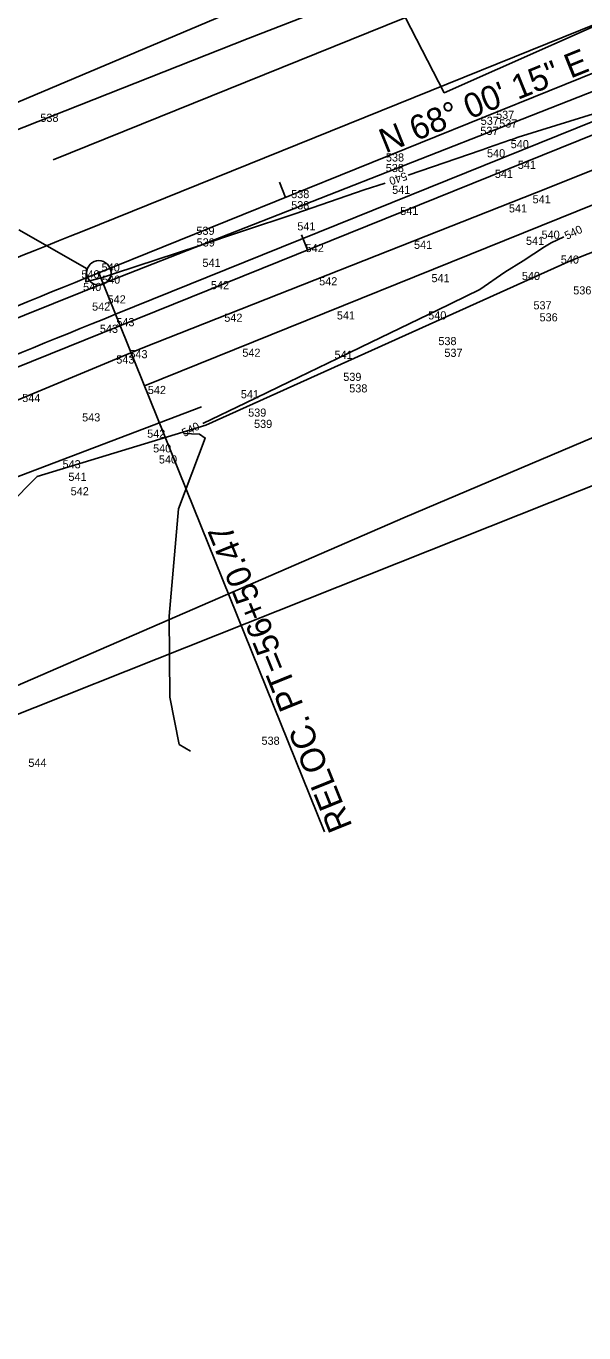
# Model space of a CAD drawing. Extents: x 1787461 to 1970323, y 938412 to 1118748.
# Drawn here: x 1967349.3 to 1967486.5, y 1117453.4 to 1117774.7 of the extents above; entities that cross this region are included whole.
import ezdxf

# ---------------------------------------------------------------- set-up
doc = ezdxf.new("R2010")
doc.units = 0
for name, color, linetype in [('Default', 7, 'Continuous'), ('HHA ADDITIONAL XSs', 7, 'Continuous'), ('Level 1', 7, 'Continuous'), ('RD_EX_DV_Prop', 7, 'Continuous'), ('RD_EX_Fence_Other', 7, 'Continuous'), ('RD_EX_Road', 7, 'Continuous'), ('RD_EX_VEG', 7, 'Continuous'), ('RD_HC_CL', 7, 'Continuous'), ('RD_HC_CL_Rel', 7, 'Continuous'), ('RD_HC_Data_Rel', 7, 'Continuous'), ('RD_HC_Data_Tic', 7, 'Continuous'), ('RD_HC_Data_Tic_Rel', 7, 'Continuous'), ('RD_PD_Final_TrvlWay', 7, 'Continuous')]:
    doc.layers.add(name, color=color, linetype=linetype)

msp = doc.modelspace()

# ---------------------------------------------------------------- linework, layer by layer
at = {"layer": 'Default'}
for points in [[(1967443.31, 1117738.03), (1967461.28, 1117744.21), (1967462.61, 1117744.65), (1967462.8, 1117744.72), (1967468.49, 1117746.69), (1967468.6, 1117746.73), (1967470.34, 1117747.38), (1967492.34, 1117754.16), (1967503.68, 1117757.74), (1967516.18, 1117761.63), (1967538.47, 1117768.72)], [(1967443.31, 1117738.03), (1967461.28, 1117744.21), (1967462.61, 1117744.65), (1967462.8, 1117744.72), (1967468.49, 1117746.69), (1967468.6, 1117746.73), (1967470.34, 1117747.38), (1967492.34, 1117754.16), (1967503.68, 1117757.74), (1967516.18, 1117761.63), (1967538.47, 1117768.72)], [(1967443.31, 1117738.03), (1967461.28, 1117744.21), (1967462.61, 1117744.65), (1967462.8, 1117744.72), (1967468.49, 1117746.69), (1967468.6, 1117746.73), (1967470.34, 1117747.38), (1967492.34, 1117754.16), (1967503.68, 1117757.74), (1967516.18, 1117761.63), (1967538.47, 1117768.72)], [(1967443.31, 1117738.03), (1967461.28, 1117744.21), (1967462.61, 1117744.65), (1967462.8, 1117744.72), (1967468.49, 1117746.69), (1967468.6, 1117746.73), (1967470.34, 1117747.38), (1967492.34, 1117754.16), (1967503.68, 1117757.74), (1967516.18, 1117761.63), (1967538.47, 1117768.72)], [(1967443.31, 1117738.03), (1967461.28, 1117744.21), (1967462.61, 1117744.65), (1967462.8, 1117744.72), (1967468.49, 1117746.69), (1967468.6, 1117746.73), (1967470.34, 1117747.38), (1967492.34, 1117754.16), (1967503.68, 1117757.74), (1967516.18, 1117761.63), (1967538.47, 1117768.72)], [(1967443.31, 1117738.03), (1967461.28, 1117744.21), (1967462.61, 1117744.65), (1967462.8, 1117744.72), (1967468.49, 1117746.69), (1967468.6, 1117746.73), (1967470.34, 1117747.38), (1967492.34, 1117754.16), (1967503.68, 1117757.74), (1967516.18, 1117761.63), (1967538.47, 1117768.72)], [(1967443.31, 1117738.03), (1967461.28, 1117744.21), (1967462.61, 1117744.65), (1967462.8, 1117744.72), (1967468.49, 1117746.69), (1967468.6, 1117746.73), (1967470.34, 1117747.38), (1967492.34, 1117754.16), (1967503.68, 1117757.74), (1967516.18, 1117761.63), (1967538.47, 1117768.72)], [(1967347.55, 1117724.58), (1967362.59, 1117715.97), (1967364.17, 1117715.07), (1967364.17, 1117714.33), (1967363.99, 1117711.78), (1967368.14, 1117712.87), (1967371.08, 1117713.86), (1967391.79, 1117720.64), (1967402.55, 1117724.29), (1967415.42, 1117728.54), (1967432.48, 1117734.38), (1967437.63, 1117736.09)], [(1967347.55, 1117724.58), (1967362.59, 1117715.97), (1967364.17, 1117715.07), (1967364.17, 1117714.33), (1967363.99, 1117711.78), (1967368.14, 1117712.87), (1967371.08, 1117713.86), (1967391.79, 1117720.64), (1967402.55, 1117724.29), (1967415.42, 1117728.54), (1967432.48, 1117734.38), (1967437.63, 1117736.09)], [(1967347.55, 1117724.58), (1967362.59, 1117715.97), (1967364.17, 1117715.07), (1967364.17, 1117714.33), (1967363.99, 1117711.78), (1967368.14, 1117712.87), (1967371.08, 1117713.86), (1967391.79, 1117720.64), (1967402.55, 1117724.29), (1967415.42, 1117728.54), (1967432.48, 1117734.38), (1967437.63, 1117736.09)], [(1967347.55, 1117724.58), (1967362.59, 1117715.97), (1967364.17, 1117715.07), (1967364.17, 1117714.33), (1967363.99, 1117711.78), (1967368.14, 1117712.87), (1967371.08, 1117713.86), (1967391.79, 1117720.64), (1967402.55, 1117724.29), (1967415.42, 1117728.54), (1967432.48, 1117734.38), (1967437.63, 1117736.09)], [(1967347.55, 1117724.58), (1967362.59, 1117715.97), (1967364.17, 1117715.07), (1967364.17, 1117714.33), (1967363.99, 1117711.78), (1967368.14, 1117712.87), (1967371.08, 1117713.86), (1967391.79, 1117720.64), (1967402.55, 1117724.29), (1967415.42, 1117728.54), (1967432.48, 1117734.38), (1967437.63, 1117736.09)], [(1967347.55, 1117724.58), (1967362.59, 1117715.97), (1967364.17, 1117715.07), (1967364.17, 1117714.33), (1967363.99, 1117711.78), (1967368.14, 1117712.87), (1967371.08, 1117713.86), (1967391.79, 1117720.64), (1967402.55, 1117724.29), (1967415.42, 1117728.54), (1967432.48, 1117734.38), (1967437.63, 1117736.09)], [(1967347.55, 1117724.58), (1967362.59, 1117715.97), (1967364.17, 1117715.07), (1967364.17, 1117714.33), (1967363.99, 1117711.78), (1967368.14, 1117712.87), (1967371.08, 1117713.86), (1967391.79, 1117720.64), (1967402.55, 1117724.29), (1967415.42, 1117728.54), (1967432.48, 1117734.38), (1967437.63, 1117736.09)], [(1967481.54, 1117722.84), (1967478.43, 1117721.37), (1967476.85, 1117720.41), (1967471.57, 1117716.93), (1967467.04, 1117714.14), (1967460.9, 1117709.88), (1967450.32, 1117704.75), (1967448.49, 1117703.86), (1967431.69, 1117695.71), (1967425.94, 1117692.94), (1967414.04, 1117687.18), (1967403.38, 1117682.06), (1967392.83, 1117676.99)], [(1967481.54, 1117722.84), (1967478.43, 1117721.37), (1967476.85, 1117720.41), (1967471.57, 1117716.93), (1967467.04, 1117714.14), (1967460.9, 1117709.88), (1967450.32, 1117704.75), (1967448.49, 1117703.86), (1967431.69, 1117695.71), (1967425.94, 1117692.94), (1967414.04, 1117687.18), (1967403.38, 1117682.06), (1967392.83, 1117676.99)], [(1967481.54, 1117722.84), (1967478.43, 1117721.37), (1967476.85, 1117720.41), (1967471.57, 1117716.93), (1967467.04, 1117714.14), (1967460.9, 1117709.88), (1967450.32, 1117704.75), (1967448.49, 1117703.86), (1967431.69, 1117695.71), (1967425.94, 1117692.94), (1967414.04, 1117687.18), (1967403.38, 1117682.06), (1967392.83, 1117676.99)], [(1967481.54, 1117722.84), (1967478.43, 1117721.37), (1967476.85, 1117720.41), (1967471.57, 1117716.93), (1967467.04, 1117714.14), (1967460.9, 1117709.88), (1967450.32, 1117704.75), (1967448.49, 1117703.86), (1967431.69, 1117695.71), (1967425.94, 1117692.94), (1967414.04, 1117687.18), (1967403.38, 1117682.06), (1967392.83, 1117676.99)], [(1967481.54, 1117722.84), (1967478.43, 1117721.37), (1967476.85, 1117720.41), (1967471.57, 1117716.93), (1967467.04, 1117714.14), (1967460.9, 1117709.88), (1967450.32, 1117704.75), (1967448.49, 1117703.86), (1967431.69, 1117695.71), (1967425.94, 1117692.94), (1967414.04, 1117687.18), (1967403.38, 1117682.06), (1967392.83, 1117676.99)], [(1967481.54, 1117722.84), (1967478.43, 1117721.37), (1967476.85, 1117720.41), (1967471.57, 1117716.93), (1967467.04, 1117714.14), (1967460.9, 1117709.88), (1967450.32, 1117704.75), (1967448.49, 1117703.86), (1967431.69, 1117695.71), (1967425.94, 1117692.94), (1967414.04, 1117687.18), (1967403.38, 1117682.06), (1967392.83, 1117676.99)], [(1967481.54, 1117722.84), (1967478.43, 1117721.37), (1967476.85, 1117720.41), (1967471.57, 1117716.93), (1967467.04, 1117714.14), (1967460.9, 1117709.88), (1967450.32, 1117704.75), (1967448.49, 1117703.86), (1967431.69, 1117695.71), (1967425.94, 1117692.94), (1967414.04, 1117687.18), (1967403.38, 1117682.06), (1967392.83, 1117676.99)], [(1967388.04, 1117674.52), (1967391.98, 1117674.37), (1967393.4, 1117673.39), (1967386.8, 1117655.96), (1967384.55, 1117629.59), (1967384.67, 1117609.63), (1967387, 1117598.04), (1967389.76, 1117596.36)], [(1967388.04, 1117674.52), (1967391.98, 1117674.37), (1967393.4, 1117673.39), (1967386.8, 1117655.96), (1967384.55, 1117629.59), (1967384.67, 1117609.63), (1967387, 1117598.04), (1967389.76, 1117596.36)], [(1967388.04, 1117674.52), (1967391.98, 1117674.37), (1967393.4, 1117673.39), (1967386.8, 1117655.96), (1967384.55, 1117629.59), (1967384.67, 1117609.63), (1967387, 1117598.04), (1967389.76, 1117596.36)], [(1967388.04, 1117674.52), (1967391.98, 1117674.37), (1967393.4, 1117673.39), (1967386.8, 1117655.96), (1967384.55, 1117629.59), (1967384.67, 1117609.63), (1967387, 1117598.04), (1967389.76, 1117596.36)], [(1967388.04, 1117674.52), (1967391.98, 1117674.37), (1967393.4, 1117673.39), (1967386.8, 1117655.96), (1967384.55, 1117629.59), (1967384.67, 1117609.63), (1967387, 1117598.04), (1967389.76, 1117596.36)], [(1967388.04, 1117674.52), (1967391.98, 1117674.37), (1967393.4, 1117673.39), (1967386.8, 1117655.96), (1967384.55, 1117629.59), (1967384.67, 1117609.63), (1967387, 1117598.04), (1967389.76, 1117596.36)], [(1967388.04, 1117674.52), (1967391.98, 1117674.37), (1967393.4, 1117673.39), (1967386.8, 1117655.96), (1967384.55, 1117629.59), (1967384.67, 1117609.63), (1967387, 1117598.04), (1967389.76, 1117596.36)]]:
    msp.add_lwpolyline(points, dxfattribs=at)
at = {"layer": 'HHA ADDITIONAL XSs'}
for p, q in [((1967355.97, 1117741.82), (1967606.98, 1117843.22)), ((1967378.44, 1117686.19), (1967629.45, 1117787.58))]:
    msp.add_line(p, q, dxfattribs=at)
for points in [[(1969266.55, 1117963.61), (1967907.56, 1117966.55), (1967403.98, 1117771.66), (1967075.57, 1117641.84)], [(1969308.89, 1117819.66), (1967912.94, 1117853.44), (1967442.55, 1117653.93), (1967107.32, 1117508.48)]]:
    msp.add_lwpolyline(points, dxfattribs=at)
at = {"layer": 'Level 1'}
for points in [[(1968647.29, 1117975.82), (1967967.92, 1117975.82), (1967727.47, 1117916.63), (1966985.13, 1117603.01)], [(1968654.57, 1117840.68), (1968058.24, 1117848.48), (1967686.38, 1117740.3), (1966964.76, 1117453.35)]]:
    msp.add_lwpolyline(points, dxfattribs=at)
at = {"layer": 'RD_EX_DV_Prop'}
msp.add_line((1966769.51, 1117457.48), (1967696.84, 1117832.06), dxfattribs=at)
at = {"layer": 'RD_EX_Fence_Other'}
msp.add_lwpolyline([(1967289.05, 1117594.53), (1967288.6, 1117597.38), (1967294.91, 1117606.13), (1967308.72, 1117618.25), (1967325.85, 1117637.29), (1967332.75, 1117652.49), (1967333.91, 1117658.84), (1967392.48, 1117681.09)], dxfattribs=at)
at = {"layer": 'RD_EX_Road'}
for points in [[(1966768.28, 1117466.83), (1966868.93, 1117506.7), (1966969.96, 1117548.31), (1967069.86, 1117589.6), (1967171.37, 1117630.89), (1967269.56, 1117671.02), (1967319.89, 1117691.93), (1967370.29, 1117712.23), (1967469.03, 1117750.91), (1967565.44, 1117788.86), (1967660.02, 1117826.88), (1967693.17, 1117840.55), (1967696.66, 1117832.16)], [(1967338.81, 1117679.22), (1967378.03, 1117695.56), (1967474.86, 1117733.75), (1967572.69, 1117772.86), (1967666.47, 1117810.1), (1967700.41, 1117823.36), (1967696.66, 1117832.16)]]:
    msp.add_lwpolyline(points, dxfattribs=at)
at = {"layer": 'RD_EX_VEG'}
for points in [[(1967420.8, 1117819.08), (1967452.15, 1117758.28), (1967558.57, 1117805.53), (1967843.24, 1117926.43), (1967916.63, 1117956.61), (1968008.44, 1117968.2), (1968060.25, 1117967.44), (1968104.58, 1117972.69), (1968157.63, 1117966.15), (1968211.15, 1117963.44), (1968421.93, 1117955.99), (1968535.19, 1117951.62)], [(1967302.31, 1117610.37), (1967337.76, 1117649.58), (1967352.05, 1117663.92), (1967393.53, 1117676.59), (1967483.38, 1117717.02), (1967710.35, 1117806.03), (1967888.86, 1117873.57), (1967928.06, 1117882.04), (1967957.92, 1117887.35), (1967975.7, 1117893.86), (1968013.09, 1117903.71), (1968102.91, 1117899.22), (1968154.08, 1117904.84), (1968208.62, 1117905.24), (1968319.32, 1117902.87), (1968421.81, 1117901.58), (1968527.92, 1117886.31)]]:
    msp.add_lwpolyline(points, dxfattribs=at)
at = {"layer": 'RD_HC_CL'}
msp.add_line((1966769.51, 1117457.48), (1967848.24, 1117893.22), dxfattribs=at)
at = {"layer": 'RD_HC_CL_Rel'}
msp.add_line((1967367.21, 1117714.01), (1967618.21, 1117815.4), dxfattribs=at)
msp.add_arc((1969513.16, 1112401.48), 5729.58, 111.995838, 114.000153, dxfattribs=at)
at = {"layer": 'RD_HC_Data_Rel'}
msp.add_line((1967367.21, 1117714.01), (1967422.74, 1117576.52), dxfattribs=at)
for radius in [3, 0.282]:
    msp.add_circle((1967367.21, 1117714.01), radius, dxfattribs=at)
at = {"layer": 'RD_HC_Data_Tic'}
msp.add_line((1967418.56, 1117719.65), (1967417.06, 1117723.36), dxfattribs=at)
at = {"layer": 'RD_HC_Data_Tic_Rel'}
msp.add_line((1967413.13, 1117732.56), (1967411.63, 1117736.27), dxfattribs=at)
at = {"layer": 'RD_PD_Final_TrvlWay'}
for p, q in [((1967363.09, 1117724.21), (1967614.09, 1117825.6)), ((1967371.33, 1117703.81), (1967622.33, 1117805.2))]:
    msp.add_line(p, q, dxfattribs=at)
for radius, start, end in [(5740.58, 111.995838, 114.000153), (5718.58, 111.99584, 114.00015)]:
    msp.add_arc((1969513.16, 1112401.48), radius, start, end, dxfattribs=at)

# ---------------------------------------------------------------- texts
at = {"layer": 'Default'}
for s, p in [('537', (1967464.92, 1117751.87)), ('538', (1967352.83, 1117751.13)), ('537', (1967461.13, 1117750.4)), ('537', (1967465.67, 1117749.74)), ('537', (1967461.04, 1117747.92)), ('540', (1967462.68, 1117742.41)), ('540', (1967468.51, 1117744.66)), ('538', (1967437.78, 1117738.78)), ('538', (1967437.82, 1117741.38)), ('541', (1967470.26, 1117739.55)), ('541', (1967464.61, 1117737.34)), ('538', (1967414.52, 1117732.37)), ('541', (1967439.35, 1117733.43)), ('538', (1967414.52, 1117729.63)), ('541', (1967473.9, 1117731.1)), ('541', (1967441.34, 1117728.23)), ('541', (1967468.07, 1117728.86)), ('539', (1967391.21, 1117723.35)), ('541', (1967416.03, 1117724.45)), ('539', (1967391.27, 1117720.49)), ('541', (1967444.73, 1117719.9)), ('541', (1967472.27, 1117720.88)), ('540', (1967476.09, 1117722.39)), ('542', (1967418.07, 1117719.11)), ('540', (1967480.83, 1117716.27)), ('540', (1967367.9, 1117714.34)), ('541', (1967392.7, 1117715.46)), ('540', (1967362.93, 1117712.65)), ('540', (1967368.01, 1117711.34)), ('542', (1967394.79, 1117709.99)), ('542', (1967421.4, 1117710.93)), ('541', (1967449.02, 1117711.71)), ('540', (1967471.26, 1117712.24)), ('540', (1967363.35, 1117709.54)), ('536', (1967483.89, 1117708.7)), ('542', (1967365.55, 1117704.71)), ('542', (1967369.37, 1117706.48)), ('537', (1967474.1, 1117705.02)), ('543', (1967371.52, 1117700.88)), ('542', (1967398.07, 1117701.97)), ('541', (1967425.76, 1117702.54)), ('540', (1967448.22, 1117702.55)), ('536', (1967475.6, 1117702.07)), ('543', (1967367.47, 1117699.25)), ('538', (1967450.72, 1117696.23)), ('543', (1967371.51, 1117691.69)), ('543', (1967374.73, 1117693.01)), ('542', (1967402.51, 1117693.37)), ('541', (1967425.18, 1117692.85)), ('537', (1967452.2, 1117693.34)), ('539', (1967427.33, 1117687.43)), ('542', (1967379.26, 1117684.2)), ('538', (1967428.8, 1117684.6)), ('544', (1967348.38, 1117682.24)), ('541', (1967402.14, 1117683.16)), ('539', (1967403.94, 1117678.64)), ('543', (1967363.1, 1117677.47)), ('539', (1967405.39, 1117675.87)), ('542', (1967379.1, 1117673.46)), ('540', (1967380.56, 1117669.84)), ('543', (1967358.29, 1117665.94)), ('540', (1967381.99, 1117667.13)), ('541', (1967359.73, 1117662.85)), ('542', (1967360.29, 1117659.3)), ('538', (1967407.22, 1117597.96)), ('544', (1967349.88, 1117592.52))]:
    msp.add_text(s, height=2, dxfattribs=at).set_placement(p)
for rotation, p in [(198.838, (1967442.62, 1117738.84)), (198.838, (1967442.62, 1117738.84)), (198.838, (1967442.62, 1117738.84)), (198.838, (1967442.62, 1117738.84)), (198.838, (1967442.62, 1117738.84)), (198.838, (1967442.62, 1117738.84)), (198.838, (1967442.62, 1117738.84)), (25.3284, (1967482.32, 1117722.1)), (25.3284, (1967482.32, 1117722.1)), (25.3284, (1967482.32, 1117722.1)), (25.3284, (1967482.32, 1117722.1)), (25.3284, (1967482.32, 1117722.1)), (25.3284, (1967482.32, 1117722.1)), (25.3284, (1967482.32, 1117722.1)), (27.2658, (1967388.27, 1117673.61)), (27.2658, (1967388.27, 1117673.61)), (27.2658, (1967388.27, 1117673.61)), (27.2658, (1967388.27, 1117673.61)), (27.2658, (1967388.27, 1117673.61)), (27.2658, (1967388.27, 1117673.61)), (27.2658, (1967388.27, 1117673.61))]:
    msp.add_text('540', height=2, rotation=rotation, dxfattribs=at).set_placement(p)
at = {"layer": 'RD_HC_Data_Rel'}
for s, rotation, p in [('N 68%%d 00\' 15" E', 21.9958, (1967437.71, 1117743.35)), ('RELOC. PT=56+50.47', 111.9958, (1967429.63, 1117577.97))]:
    msp.add_text(s, height=6, rotation=rotation, dxfattribs=at).set_placement(p)

doc.saveas('drawing.dxf')
